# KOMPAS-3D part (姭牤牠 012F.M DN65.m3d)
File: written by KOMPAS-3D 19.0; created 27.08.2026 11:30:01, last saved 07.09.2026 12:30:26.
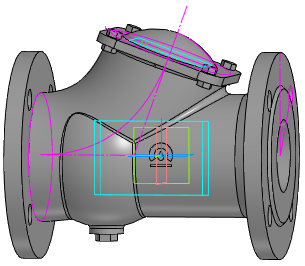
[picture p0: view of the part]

Document properties: Автор: Энергия; Полное имя файла: Z:\3.Личные\kachalov\001_3d для проектировщиков\х.х Тип 012F\012F.M\Клапан 012F.M DN65.m3d

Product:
- Part/product: (unnamed)  | designation Клапан 012F.M DN65
    Масса: 22.1556

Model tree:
1. Эскиз:1
2. Элемент вращения:1
     Угол 1 = 360
3. Эскиз:2  (with: Элемент вращения:1)
4. Перпендикулярная плоскость:1
5. Эскиз:3
6. Эскиз:12  (with: Элемент вращения:1)
7. Элемент по сечениям:1
8. Эскиз:7
9. Элемент выдавливания:2
     Расстояние 2 = 8
10. Эскиз:9  (with: Элемент выдавливания:2)
11. Элемент вращения:2
     Угол 1 = 360
12. Эскиз:10  (with: Элемент вращения:1)
13. Элемент выдавливания:3  (with: Элемент вращения:1)
     Расстояние 2 = 16
14. Массив по концентрической сетке:1  (with: Элемент выдавливания:3, Эскиз:10, Элемент вращения:1)  (4 pattern instances)
     Шаг 2 = 360
15. Эскиз:11  (with: Элемент вращения:1)
16. Элемент выдавливания:4  (with: Элемент вращения:1)
     Расстояние 2 = 16
17. Массив по концентрической сетке:2  (with: Элемент выдавливания:4, Эскиз:11, Элемент вращения:1)  (4 pattern instances)
     Шаг 2 = 360
18. Скругление:6  (with: Элемент выдавливания:2)
     Радиус = 3
19. Эскиз:13  (with: Элемент выдавливания:2)
20. Элемент выдавливания:5  (with: Элемент выдавливания:2)
     Расстояние 1 = 5.5; Расстояние 2 = 13.5; Смещение 2 = 5.5
21. Массив по концентрической сетке:3  (with: Элемент выдавливания:5, Эскиз:9, Эскиз:13, Элемент вращения:2)  (4 pattern instances)
     Шаг 2 = 360
22. Касательная плоскость:1  (with: Элемент вращения:1)
     Угол = 90
23. Смещенная плоскость:1
     Расстояние = 1
24. Эскиз:14
25. Элемент выдавливания:6  (with: Элемент вращения:1)
     Расстояние 1 = -1.00038; Расстояние 2 = 1
26. Эскиз:15  (with: Элемент вращения:1)
27. Элемент вращения:3  (with: Элемент вращения:1)
     Угол 1 = 360
28. Скругление:10  (with: Элемент вращения:3, Элемент по сечениям:1)
     Радиус = 5
29. Эскиз:16
30. Элемент выдавливания:7
     Расстояние 1 = 70
31. Эскиз:17  (with: Элемент выдавливания:7)
32. Элемент выдавливания:8
     Расстояние 1 = 6.5
33. Эскиз:18  (with: Элемент вращения:1)
34. Элемент выдавливания:9
     Расстояние 2 = 240
35. Скругление:11  (with: Элемент выдавливания:2)
     Радиус = 20
36. Скругление:12  (with: Элемент выдавливания:7)
     Радиус = 3
37. Эскиз:19  (with: Скругление:11, Элемент выдавливания:5)
38. Эскиз:20  (with: Скругление:11)

Expressions: Dn/2; D/2; D2/2; D2/2-5; 360/(2*n); 360/(n*2); D2-6; D2-5; (D2+5)/2
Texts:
  Клапан 012F.M DN65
